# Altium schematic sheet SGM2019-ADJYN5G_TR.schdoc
size 127 x 101 mm
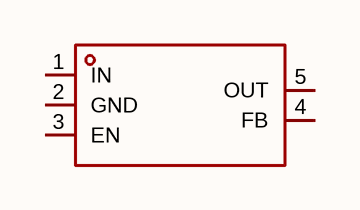
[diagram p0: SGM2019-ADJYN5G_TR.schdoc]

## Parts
U?  jsm2019-adjyn5g/tr  [SOT-23-5_L2.9-W1.6-P0.95-LS2.8-BR]  (value not drawn)

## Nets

Not connected (* = marked no-connect by the designer): U? 1(IN) 2(GND) 3(EN) 4(FB) 5(OUT)

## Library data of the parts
U? = jsm2019-adjyn5g/tr: 输出极性:正极;工作电压:5.5V;输出电压:-;输出电流:300mA;电源纹波抑制比(PSRR):80dB@(100Hz);输出类型:可调;; Manufacturer: JSMSEMI(杰盛微); Symbol: SGM2019-ADJYN5G/TR; AddInBom: yes; ModelId: 7ba65df16e7b4570af156e925f9c37fe; ModelTransform: 114.173,114.173,0,90,0,0,0,0,0; Output Configuration: 正极; Voltage - Supply: 5.5V; Output Current: 300mA; standby current: 2uA; Output Type: 可调; Number of Outputs: 1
